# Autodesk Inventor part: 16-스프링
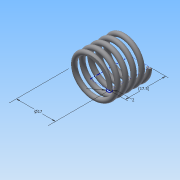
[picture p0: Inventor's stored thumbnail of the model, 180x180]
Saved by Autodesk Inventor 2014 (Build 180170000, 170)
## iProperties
Created: 2016-01
Part Number: 16-스프링
Material: 강철, 탄소
Document SubType Name: Modeling
Designer: Administrator
Density: 7.87 g/cm^3
Appearance: 반연마
Mass: 6.44159 g
Surface Area: 16.7002 cm^2
Volume: 0.818499 cm^3
Author: Administrator
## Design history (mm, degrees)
sketch "스케치1"
  geometry: L1 (0, 0)-(8.5, 0); L2 (8.5, 0)-(8.5, 17.5); L3 (8.5, 17.5)-(0, 17.5); L4 (0, 17.5)-(0, 0); C1 r 1 at (8.5, 0)
  constraints: 8 end point, 2 parallel, 1 centre point, 1 coincident, 1 horizontal, 1 perpendicular
  dimensions: "d0" = 17 diameter of L2 L4; "d1" = 17.5 distance of L1.end L2.end (derived); "d2" = 2 diameter of C1
feature "코일1" sketch "스케치1" pitch "d3" = 10; turns "d5" = 5; dims "d4" = 17.5 (= d1), "d6" = 0, angle "d7" = 90 deg, angle "d8" = 90 deg, "d9" = 0, "d10" = 0
node "작업 평면2"
sketch "스케치2"
  geometry: L1 (-7.5, 0)-(-9.5, 0) reference; 1 further point
  constraints: 1 horizontal alignment
extrude "돌출1" cut sketch "스케치2" distance "d13" = 10; taper "d14" = 0 deg
node "작업 평면3"
sketch "스케치3"
  geometry: L1 (-9.5, 0)-(-7.5, 0) reference; 1 further point
  constraints: 1 horizontal alignment
extrude "돌출2" cut sketch "스케치3" distance "d16" = 10; taper "d17" = 0 deg
node "솔리드1"
node "절단 모서리 투영1"
node "절단 모서리 투영2"
other parameters: "d12" = 0, "d15" = 17.5 (= d1)
